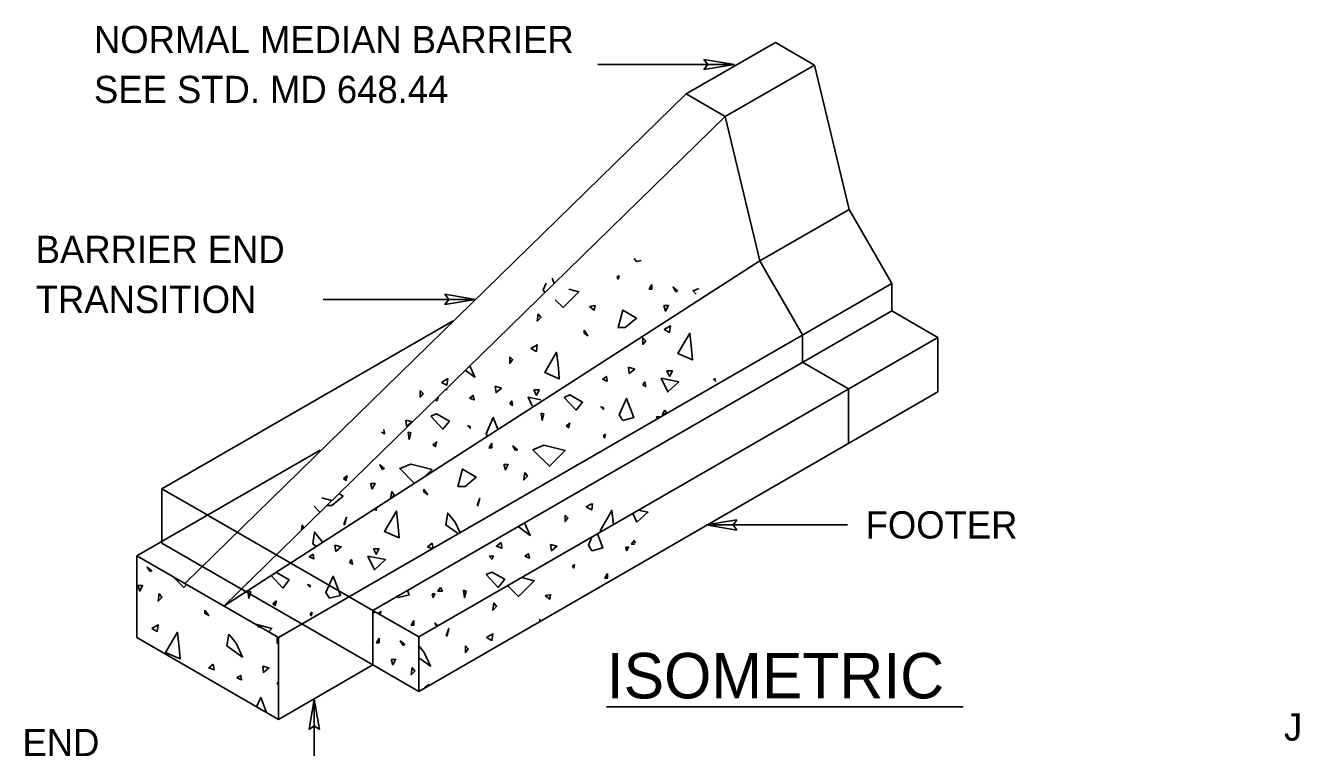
# Model space of a CAD drawing. Extents: x -0.8 to 6.5, y 10.6 to 20.8.
# Drawn here: x -0.771 to 2.035, y 19.175 to 20.765 of the extents above; entities that cross this region are included whole.
import ezdxf

# ---------------------------------------------------------------- set-up
doc = ezdxf.new("R2010")
doc.units = 0
for name, color, linetype in [('DETL-DIMS', 7, 'Continuous'), ('DETL-LINE', 7, 'Continuous'), ('DETL-NOTE', 7, 'Continuous'), ('DETL-PATT', 7, 'Continuous'), ('DETL-TITL', 7, 'Continuous')]:
    doc.layers.add(name, color=color, linetype=linetype)

msp = doc.modelspace()

# ---------------------------------------------------------------- linework, layer by layer
at = {"layer": 'DETL-DIMS'}
for p, q in [((0.7234, 20.6904), (0.7907, 20.6792)), ((0.7234, 20.6904), (0.7319, 20.6792)), ((0.4899, 20.6792), (0.7907, 20.6792)), ((0.7234, 20.6681), (0.7907, 20.6792)), ((0.7234, 20.6681), (0.7319, 20.6792)), ((-0.1148, 20.1618), (0.2203, 20.1618)), ((0.1531, 20.1731), (0.2203, 20.1618)), ((0.1531, 20.1731), (0.1615, 20.1618)), ((0.1531, 20.1506), (0.2203, 20.1618)), ((0.1531, 20.1506), (0.1615, 20.1618)), ((0.796, 19.6762), (0.7289, 19.6651)), ((0.796, 19.6762), (0.7877, 19.6651)), ((1.0398, 19.6651), (0.7289, 19.6651)), ((0.796, 19.6537), (0.7289, 19.6651)), ((0.796, 19.6537), (0.7877, 19.6651)), ((-0.1456, 19.2143), (-0.1345, 19.2814)), ((-0.1345, 18.9657), (-0.1345, 19.2814)), ((-0.1233, 19.2143), (-0.1345, 19.2814)), ((-0.1456, 19.2143), (-0.1345, 19.2226)), ((-0.1233, 19.2143), (-0.1345, 19.2226))]:
    msp.add_line(p, q, dxfattribs=at)
at = {"layer": 'DETL-LINE'}
for p, q in [((0.8812, 20.7274), (0.6846, 20.6142)), ((0.967, 20.6777), (0.8812, 20.7274)), ((0.967, 20.6777), (0.7704, 20.5646)), ((1.0433, 20.3601), (0.967, 20.6777)), ((0.6846, 20.6142), (-0.4189, 19.5366)), ((0.7704, 20.5646), (0.6846, 20.6142)), ((0.7704, 20.5646), (-0.3331, 19.4869)), ((0.8465, 20.247), (0.7704, 20.5646)), ((1.0433, 20.3601), (0.8465, 20.247)), ((1.0738, 20.3073), (1.0433, 20.3601)), ((1.1007, 20.2608), (1.0635, 20.3249)), ((1.1377, 20.1965), (1.1007, 20.2608)), ((0.8465, 20.247), (-0.3331, 19.4869)), ((0.877, 20.1941), (0.8465, 20.247)), ((0.904, 20.1475), (0.8669, 20.2118)), ((-0.2133, 19.4166), (1.1377, 20.1965)), ((1.1377, 20.1365), (1.1377, 20.1965)), ((0.941, 20.0833), (0.904, 20.1475)), ((-0.0055, 19.4766), (1.1377, 20.1365)), ((1.239, 20.078), (1.1377, 20.1365)), ((-0.4699, 19.7447), (0.1715, 20.1148)), ((0.0958, 19.4181), (1.239, 20.078)), ((0.941, 20.0233), (0.941, 20.0833)), ((1.239, 19.958), (1.239, 20.078)), ((1.0423, 19.9648), (0.941, 20.0233)), ((0.0958, 19.2981), (1.239, 19.958)), ((1.0423, 19.8449), (1.0423, 19.9648)), ((-0.5251, 19.5966), (-0.1215, 19.8295)), ((-0.4699, 19.6246), (-0.4699, 19.7447)), ((-0.3686, 19.6862), (-0.4699, 19.7447)), ((-0.0055, 19.4766), (-0.3679, 19.6859)), ((-0.0055, 19.3564), (-0.4699, 19.6246)), ((-0.2133, 19.4166), (-0.5251, 19.5966)), ((-0.5251, 19.4166), (-0.5251, 19.5966)), ((0.0958, 19.4181), (-0.0055, 19.4766)), ((-0.0055, 19.3564), (-0.0055, 19.4766)), ((0.0958, 19.2981), (0.0958, 19.4181)), ((-0.2133, 19.2365), (-0.5251, 19.4166)), ((-0.2133, 19.2365), (-0.2133, 19.4166)), ((-0.0055, 19.3564), (-0.2133, 19.2365)), ((0.0958, 19.2981), (-0.0055, 19.3564))]:
    msp.add_line(p, q, dxfattribs=at)
at = {"layer": 'DETL-PATT'}
for points in [[(0.4759, 20.2775), (0.4761, 20.2771)], [(0.4786, 20.2796), (0.4784, 20.2796)], [(0.5702, 20.2521), (0.5749, 20.245), (0.5852, 20.2476)], [(0.3941, 20.1971), (0.3896, 20.2086)], [(0.3763, 20.1978), (0.3698, 20.1831), (0.3736, 20.1771)], [(0.4263, 20.1843), (0.4478, 20.1786), (0.4133, 20.1441), (0.3961, 20.1611)], [(0.7067, 20.1736), (0.6997, 20.1806), (0.7127, 20.186)], [(0.1981, 20.0058), (0.2193, 19.9905), (0.208, 20.0153)], [(0.75, 19.9862), (0.7449, 19.9862), (0.7507, 19.9803)], [(0.1545, 19.963), (0.157, 19.9622), (0.1565, 19.965)], [(0.132, 19.941), (0.1348, 19.9382), (0.1386, 19.9445), (0.1353, 19.9445)], [(0.3646, 19.9403), (0.3364, 19.9463), (0.3454, 19.9273)], [(0.2696, 19.8757), (0.2596, 19.9017), (0.2438, 19.8657), (0.2471, 19.8607)], [(0.6241, 19.9), (0.6257, 19.9032), (0.6196, 19.9032), (0.6207, 19.898)], [(0.6406, 19.9095), (0.6321, 19.9095), (0.6377, 19.9177), (0.6417, 19.9102)], [(0.0132, 19.8689), (0.0203, 19.8659), (0.0187, 19.8749)], [(0.0858, 19.7569), (0.0537, 19.7889), (0.0782, 19.799), (0.1248, 19.787), (0.1103, 19.7727)], [(0.4451, 19.7967), (0.4419, 19.7962), (0.4429, 19.7954)], [(-0.107, 19.7079), (-0.0957, 19.7079), (-0.0712, 19.7284), (-0.0803, 19.7339)], [(0.0362, 19.7249), (0.0417, 19.7304), (0.036, 19.7385), (0.0337, 19.7232)], [(0.5897, 19.7332), (0.5897, 19.7332), (0.5897, 19.7332)], [(-0.122, 19.6932), (-0.1346, 19.7059)], [(-0.1178, 19.7244), (-0.0958, 19.7187)], [(-0.0028, 19.6997), (0.0018, 19.6972), (0.0027, 19.7032)], [(0.4758, 19.7114), (0.4644, 19.7049), (0.4764, 19.6985), (0.4783, 19.7119)], [(0.5669, 19.69), (0.5761, 19.6711), (0.6001, 19.693), (0.5797, 19.6974)], [(0.1865, 19.6472), (0.1756, 19.6709), (0.1593, 19.691), (0.1555, 19.6651), (0.183, 19.6452)], [(0.3145, 19.6612), (0.3411, 19.6419), (0.3286, 19.6694)], [(0.4984, 19.6506), (0.4948, 19.6521), (0.5211, 19.6967), (0.5246, 19.6656)], [(-0.1573, 19.6587), (-0.1611, 19.6642), (-0.1628, 19.6532)], [(-0.1165, 19.6266), (-0.1176, 19.6291), (-0.134, 19.6492), (-0.1378, 19.6234), (-0.1301, 19.6177)], [(0.4766, 19.6379), (0.4691, 19.6206), (0.4771, 19.6081), (0.5013, 19.6144), (0.4893, 19.6452)], [(0.127, 19.6129), (0.1251, 19.6247), (0.1151, 19.6166), (0.1263, 19.6126)], [(0.5707, 19.6226), (0.5641, 19.6226), (0.5697, 19.6307), (0.5727, 19.6251)], [(-0.2298, 19.5534), (-0.2041, 19.5259), (-0.1896, 19.5437), (-0.218, 19.5601), (-0.224, 19.5572)], [(-0.4159, 19.5334), (-0.4219, 19.5274), (-0.4444, 19.5501)], [(-0.2848, 19.5341), (-0.2713, 19.5466), (-0.272, 19.5467)], [(0.3226, 19.5489), (0.3499, 19.5419), (0.3155, 19.5072), (0.2916, 19.5311)], [(0.0487, 19.5077), (0.0507, 19.5047), (0.0747, 19.5109), (0.071, 19.5206)], [(0.4473, 19.5009), (0.4469, 19.5011), (0.4468, 19.5007)], [(-0.0055, 19.4711), (-0.0018, 19.4721), (-0.0032, 19.4751)], [(0.0107, 19.4673), (0.0123, 19.4744), (0.008, 19.4706), (0.0095, 19.4679)], [(-0.2641, 19.4464), (-0.2281, 19.4371), (-0.2356, 19.4296)], [(0.1386, 19.4428), (0.1313, 19.4486), (0.136, 19.4413)], [(0.3644, 19.4531), (0.3619, 19.4569), (0.3619, 19.4518)], [(-0.2576, 19.4421), (-0.2583, 19.4406), (-0.2563, 19.4406), (-0.2561, 19.4413)], [(-0.216, 19.4181), (-0.216, 19.4041), (-0.2133, 19.4076)], [(-0.2133, 19.4158), (-0.2151, 19.4176)], [(0.0958, 19.3721), (0.1215, 19.3538), (0.1076, 19.3839), (0.0958, 19.3984)], [(-0.2133, 19.3193), (-0.216, 19.3153), (-0.2133, 19.3136)], [(0.1181, 19.3109), (0.1176, 19.3134), (0.1095, 19.3076), (0.1111, 19.3069)], [(-0.2396, 19.2518), (-0.2525, 19.2851), (-0.2616, 19.2644)]]:
    msp.add_lwpolyline(points, dxfattribs=at)
for points in [[(0.5366, 20.2146), (0.5322, 20.2108), (0.5346, 20.2065)], [(0.6091, 20.1945), (0.6032, 20.1845), (0.6091, 20.1845)], [(0.6619, 20.1786), (0.6657, 20.1806), (0.6556, 20.1888)], [(0.4718, 20.146), (0.4819, 20.1378), (0.4838, 20.148)], [(0.6354, 20.148), (0.6392, 20.136), (0.6456, 20.148)], [(0.3589, 20.1301), (0.3566, 20.1138), (0.3648, 20.122)], [(0.5504, 20.0995), (0.5749, 20.1201), (0.5447, 20.1378), (0.5346, 20.0995)], [(0.4598, 20.0937), (0.4598, 20.0875), (0.4679, 20.0817)], [(0.6359, 20.0952), (0.6479, 20.089), (0.6497, 20.1033)], [(0.5894, 20.077), (0.5894, 20.0625), (0.5956, 20.0707)], [(0.6964, 20.0525), (0.6982, 20.0285), (0.6661, 20.0423), (0.6926, 20.087)], [(0.2961, 20.0352), (0.2961, 20.0208), (0.3023, 20.029)], [(0.3426, 20.0533), (0.3546, 20.0472), (0.3566, 20.0615)], [(0.4031, 20.0107), (0.4051, 19.9867), (0.3729, 20.0007), (0.3993, 20.0452)], [(0.5572, 20.0122), (0.5591, 19.9982), (0.5711, 20.0083)], [(0.1456, 19.979), (0.1576, 19.9728), (0.1595, 19.9872)], [(0.5006, 19.9862), (0.5106, 19.9818), (0.5088, 19.992)], [(0.5894, 19.9738), (0.5956, 19.9698), (0.5936, 19.98)], [(0.6297, 19.9882), (0.6441, 19.9578), (0.6681, 19.98)], [(0.6421, 20.004), (0.6479, 19.992), (0.6541, 20.004)], [(0.099, 19.9608), (0.099, 19.9465), (0.1053, 19.9547)], [(0.2073, 19.9445), (0.2173, 19.9402), (0.2155, 19.9502)], [(0.264, 19.9703), (0.2658, 19.9565), (0.2778, 19.9665)], [(0.3489, 19.9622), (0.3546, 19.9502), (0.3609, 19.9622)], [(0.4156, 19.9458), (0.4419, 19.9177), (0.4564, 19.9353), (0.4281, 19.9517)], [(0.2961, 19.932), (0.3023, 19.9282), (0.3005, 19.9382)], [(0.5024, 19.9233), (0.4968, 19.9253), (0.5024, 19.9195)], [(0.5452, 19.895), (0.5692, 19.9013), (0.5529, 19.9435), (0.5371, 19.9075)], [(0.0668, 19.896), (0.0688, 19.8822), (0.0808, 19.8922)], [(0.1223, 19.9042), (0.1488, 19.8759), (0.1631, 19.8935), (0.1348, 19.9098)], [(0.3651, 19.9113), (0.3676, 19.895), (0.3714, 19.9095)], [(0.072, 19.8695), (0.0743, 19.8532), (0.0782, 19.8677)], [(0.2091, 19.8815), (0.2035, 19.8835), (0.2091, 19.8777)], [(0.4199, 19.883), (0.4256, 19.8792), (0.4281, 19.8894)], [(0.1266, 19.8412), (0.1325, 19.8374), (0.1348, 19.8475)], [(0.2563, 19.8447), (0.2505, 19.8345), (0.2563, 19.8345)], [(0.309, 19.8289), (0.3128, 19.8307), (0.3028, 19.8389)], [(0.3714, 19.8409), (0.4179, 19.8289), (0.3834, 19.7942), (0.3469, 19.8307)], [(0.5068, 19.8649), (0.5024, 19.861), (0.5049, 19.8567)], [(0.0158, 19.787), (0.0197, 19.7889), (0.0095, 19.797)], [(0.1976, 19.7495), (0.2221, 19.7702), (0.192, 19.788), (0.1818, 19.7495)], [(0.2826, 19.798), (0.2865, 19.786), (0.2926, 19.798)], [(-0.0705, 19.7669), (-0.0647, 19.763), (-0.0623, 19.7732)], [(-0.0107, 19.7562), (-0.0068, 19.7442), (-0.0005, 19.7562)], [(0.3291, 19.7804), (0.3268, 19.764), (0.3349, 19.7722)], [(0.107, 19.7439), (0.107, 19.7375), (0.1151, 19.7319)], [(0.2241, 19.7074), (0.226, 19.7074), (0.2298, 19.7237)], [(-0.0692, 19.6656), (-0.0673, 19.6656), (-0.0635, 19.6819)], [(0.0503, 19.6607), (0.0522, 19.6367), (0.02, 19.6507), (0.0465, 19.6954)], [(0.4179, 19.6865), (0.4179, 19.6722), (0.4241, 19.6804)], [(-0.089, 19.6206), (-0.087, 19.6066), (-0.075, 19.6166)], [(0.2768, 19.6261), (0.2668, 19.6179), (0.2788, 19.6136)], [(0.3858, 19.6217), (0.3878, 19.6079), (0.3998, 19.6179)], [(0.5516, 19.6162), (0.5534, 19.6081), (0.5577, 19.6162)], [(-0.1455, 19.5946), (-0.1355, 19.5902), (-0.1373, 19.6004)], [(-0.0568, 19.5821), (-0.0505, 19.5782), (-0.0525, 19.5884)], [(-0.0165, 19.5964), (-0.002, 19.5662), (0.022, 19.5884)], [(-0.004, 19.6124), (0.0018, 19.6004), (0.008, 19.6124)], [(0.2505, 19.5959), (0.2566, 19.5896), (0.2605, 19.5959)], [(0.3291, 19.5959), (0.3393, 19.5916), (0.3373, 19.6016)], [(-0.4963, 19.5621), (-0.4924, 19.5639), (-0.5026, 19.5721)], [(0.2441, 19.5556), (0.2706, 19.5272), (0.285, 19.5451), (0.2566, 19.5612)], [(0.4388, 19.5779), (0.4344, 19.5741), (0.4369, 19.5697)], [(0.5113, 19.5577), (0.5054, 19.5476), (0.5113, 19.5476)], [(-0.5228, 19.5312), (-0.5189, 19.5192), (-0.5126, 19.5312)], [(-0.1436, 19.5317), (-0.1493, 19.5336), (-0.1436, 19.5279)], [(-0.101, 19.5034), (-0.077, 19.5096), (-0.0932, 19.5519), (-0.1091, 19.5159)], [(-0.4761, 19.5136), (-0.4786, 19.4972), (-0.4704, 19.5054)], [(-0.281, 19.5197), (-0.2785, 19.5034), (-0.2746, 19.5177)], [(0.1251, 19.5129), (0.127, 19.5047), (0.1313, 19.5129)], [(0.1433, 19.5272), (0.1476, 19.5191), (0.1376, 19.5191)], [(0.1938, 19.5211), (0.1961, 19.5047), (0.2, 19.5191)], [(0.3739, 19.5092), (0.3841, 19.5011), (0.3859, 19.5111)], [(-0.3753, 19.4771), (-0.3753, 19.4708), (-0.3671, 19.4651)], [(-0.2261, 19.4914), (-0.2205, 19.4876), (-0.218, 19.4976)], [(-0.1393, 19.4731), (-0.1436, 19.4693), (-0.1413, 19.4649)], [(0.2611, 19.4934), (0.2588, 19.4771), (0.267, 19.4852)], [(-0.4924, 19.4368), (-0.4804, 19.4304), (-0.4786, 19.4449)], [(0.0848, 19.4543), (0.079, 19.4443), (0.0848, 19.4443)], [(-0.4319, 19.3939), (-0.4301, 19.3699), (-0.4623, 19.3839), (-0.4358, 19.4286)], [(-0.3229, 19.4243), (-0.3269, 19.3983), (-0.2928, 19.3738), (-0.3068, 19.4041)], [(0.156, 19.4204), (0.158, 19.4204), (0.1618, 19.4368)], [(0.2448, 19.4166), (0.2568, 19.4104), (0.2588, 19.4248)], [(0.0082, 19.4154), (0.0023, 19.4053), (0.0082, 19.4053)], [(0.061, 19.3996), (0.0648, 19.4014), (0.0547, 19.4096)], [(0.1983, 19.3984), (0.1983, 19.3839), (0.2045, 19.3921)], [(0.0345, 19.3688), (0.0385, 19.3568), (0.0447, 19.3688)], [(-0.3571, 19.3579), (-0.3671, 19.3498), (-0.3551, 19.3454)], [(-0.3048, 19.3278), (-0.2948, 19.3234), (-0.2966, 19.3334)], [(-0.2481, 19.3536), (-0.2463, 19.3398), (-0.2343, 19.3498)], [(0.0812, 19.3511), (0.0787, 19.3348), (0.0868, 19.3429)]]:
    msp.add_lwpolyline(points, close=True, dxfattribs=at)
at = {"layer": 'DETL-TITL'}
msp.add_line((0.5088, 19.2644), (1.2948, 19.2644), dxfattribs=at)

# ---------------------------------------------------------------- texts
at = {"layer": 'DETL-NOTE'}
for s, p in [('NORMAL MEDIAN BARRIER', (-0.6197, 20.7042)), ('SEE STD. MD 648.44', (-0.6197, 20.5942)), ('BARRIER END', (-0.748, 20.2418)), ('TRANSITION', (-0.748, 20.1318)), ('FOOTER', (1.0798, 19.635)), ('J', (2.0012, 19.1897)), ('END', (-0.7771, 19.1556))]:
    msp.add_text(s, height=0.06, dxfattribs=at).set_placement(p)
at = {"layer": 'DETL-TITL'}
msp.add_text('ISOMETRIC', height=0.1, dxfattribs=at).set_placement((0.5096, 19.2828))

doc.saveas('drawing.dxf')
